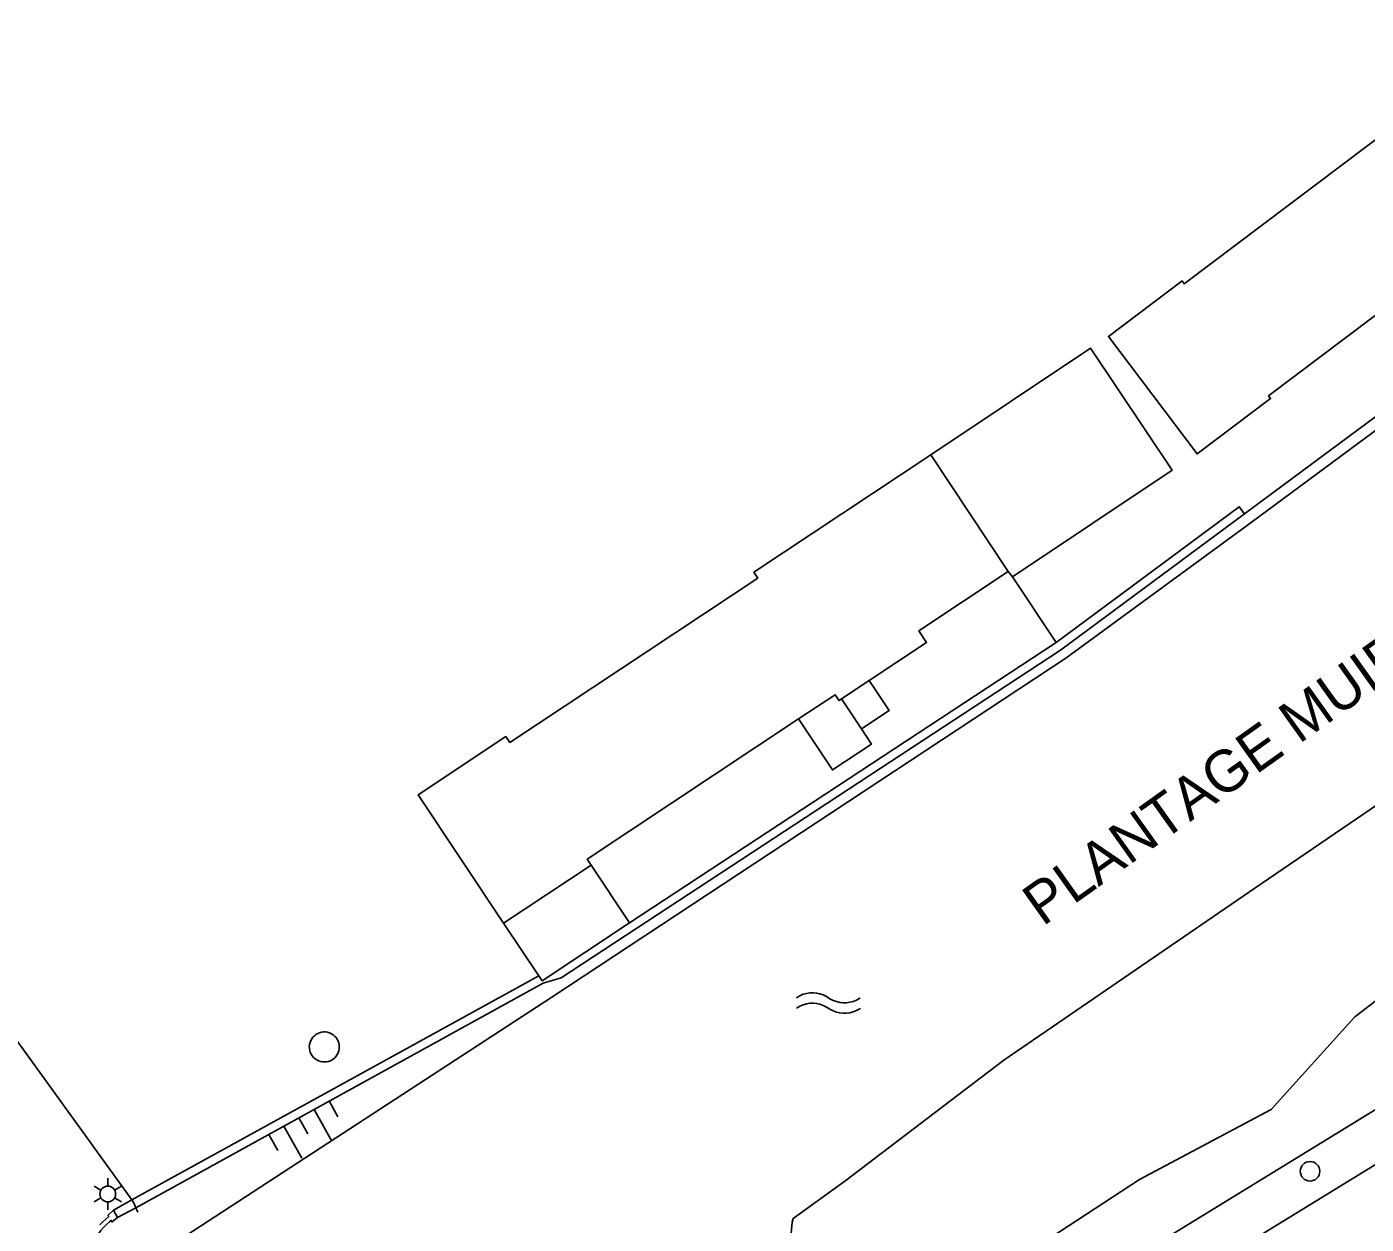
# Model space of a CAD drawing. Extents: x 122462 to 123306, y 485548 to 486417.
# Drawn here: x 123082 to 123158.7, y 486348.4 to 486417 of the extents above; entities that cross this region are included whole.
import ezdxf

# ---------------------------------------------------------------- set-up
doc = ezdxf.new("R2010")
doc.units = 0
for name, color, linetype in [('Level 1', 7, 'Continuous'), ('Level 15', 7, 'Continuous'), ('Level 16', 7, 'Continuous'), ('Level 17', 7, 'Continuous'), ('Level 19', 7, 'Continuous'), ('Level 2', 7, 'Continuous'), ('Level 20', 7, 'Continuous'), ('Level 24', 7, 'Continuous'), ('Level 41', 7, 'Continuous'), ('Level 50', 7, 'Continuous'), ('Level 53', 7, 'Continuous'), ('Level 55', 7, 'Continuous'), ('Level 57', 7, 'Continuous'), ('N werkgrens', 7, 'Continuous'), ('N-WE-GR-BOOM_STAM-G', 7, 'Continuous')]:
    doc.layers.add(name, color=color, linetype=linetype)

msp = doc.modelspace()

# ---------------------------------------------------------------- linework, layer by layer
at = {"layer": 'Level 1'}
msp.add_lwpolyline([(123167.795, 486416.958), (123166.225, 486415.776), (123166.105, 486415.936), (123160.112, 486411.424), (123160.232, 486411.265), (123148.252, 486402.244), (123148.132, 486402.404), (123143.918, 486399.231), (123148.989, 486392.497), (123153.203, 486395.67), (123153.083, 486395.83), (123165.062, 486404.849), (123165.182, 486404.69), (123171.175, 486409.202), (123171.055, 486409.362), (123181.145, 486416.958)], dxfattribs=at)
at = {"layer": 'Level 15'}
for p, q in [((123116.491, 486365.658), (123140.926, 486381.7)), ((123088.001, 486349.781), (123111.309, 486362.623)), ((123086.952, 486349.203), (123088.001, 486349.781)), ((123088.234, 486349.339), (123087.19, 486348.785)), ((123087.19, 486348.785), (123086.952, 486349.203))]:
    msp.add_line(p, q, dxfattribs=at)
for points in [[(123140.926, 486381.7), (123151.405, 486389.472), (123151.706, 486389.073)], [(123151.706, 486389.073), (123141.17, 486381.258), (123112.593, 486362.502), (123111.563, 486362.191), (123088.234, 486349.339)], [(123087.19, 486348.785), (123086.875, 486348.525), (123086.834, 486348.614), (123086.725, 486348.527), (123086.553, 486348.374), (123086.393, 486348.209), (123086.243, 486348.034), (123086.106, 486347.849), (123085.982, 486347.655), (123085.872, 486347.454), (123085.775, 486347.245), (123085.693, 486347.03), (123085.626, 486346.81), (123085.574, 486346.586), (123085.537, 486346.359), (123085.516, 486346.129), (123085.511, 486345.899), (123085.521, 486345.67), (123085.547, 486345.441), (123085.588, 486345.215), (123085.645, 486344.992), (123085.717, 486344.773), (123085.803, 486344.56), (123085.904, 486344.353)], [(123086.952, 486349.203), (123086.635, 486348.888), (123086.691, 486348.832), (123086.516, 486348.691), (123086.339, 486348.528), (123086.173, 486348.354)]]:
    msp.add_lwpolyline(points, dxfattribs=at)
at = {"layer": 'Level 16'}
for points in [[(123190.452, 486416.958), (123152.084, 486388.57), (123141.474, 486380.8), (123112.044, 486361.399), (123104.38, 486356.401), (123085.904, 486344.353)], [(123217.361, 486416.958), (123206.829, 486406.748), (123179.003, 486385.844), (123152.655, 486367.889), (123137.927, 486357.79), (123128.826, 486350.852), (123125.877, 486348.714), (123125.807, 486348.517), (123125.744, 486347.678)]]:
    msp.add_lwpolyline(points, dxfattribs=at)
at = {"layer": 'Level 17'}
for points in [[(123132.782, 486338.745), (123187.402, 486372.258)], [(123134.337, 486336.539), (123186.289, 486368.432)]]:
    msp.add_lwpolyline(points, dxfattribs=at)
at = {"layer": 'Level 19'}
for p, q in [((123189.359, 486416.958), (123151.706, 486389.073)), ((123138.417, 486385.457), (123140.926, 486381.7))]:
    msp.add_line(p, q, dxfattribs=at)
at = {"layer": 'Level 2'}
for p, q in [((123138.185, 486385.758), (123133.752, 486392.442)), ((123138.417, 486385.457), (123138.185, 486385.758)), ((123128.636, 486378.469), (123130.227, 486379.525)), ((123129.777, 486376.749), (123128.636, 486378.469)), ((123109.28, 486365.632), (123114.3, 486368.961)), ((123114.3, 486368.961), (123116.491, 486365.658)), ((123111.309, 486362.623), (123109.28, 486365.632))]:
    msp.add_line(p, q, dxfattribs=at)
for points in [[(123133.752, 486392.442), (123142.9, 486398.551), (123147.565, 486391.566), (123138.417, 486385.457)], [(123109.28, 486365.632), (123104.405, 486372.982), (123109.427, 486376.312), (123109.648, 486375.978), (123123.844, 486385.392), (123123.623, 486385.725), (123133.752, 486392.442)], [(123138.185, 486385.758), (123133.069, 486382.365), (123133.509, 486381.702), (123130.227, 486379.525)], [(123130.227, 486379.525), (123131.368, 486377.804), (123129.777, 486376.749)], [(123126.182, 486377.322), (123128.276, 486378.711), (123128.498, 486378.378), (123128.636, 486378.469)], [(123114.3, 486368.961), (123114.079, 486369.295), (123126.182, 486377.322)], [(123129.777, 486376.749), (123130.349, 486375.887), (123128.116, 486374.406), (123126.182, 486377.322)], [(123116.491, 486365.658), (123111.502, 486362.337), (123111.309, 486362.623)]]:
    msp.add_lwpolyline(points, dxfattribs=at)
at = {"layer": 'Level 20'}
msp.add_lwpolyline([(123227.128, 486416.958), (123226.347, 486416.118), (123214.358, 486404.642), (123207.4, 486399.966), (123200.277, 486394.449), (123191.597, 486386.324), (123182.341, 486378.222), (123175.379, 486372.758), (123164.712, 486365.388), (123158.016, 486360.276), (123153.237, 486354.953), (123145.688, 486350.946), (123140.068, 486347.272), (123131.328, 486340.807)], dxfattribs=at)
at = {"layer": 'Level 24'}
msp.add_line((123088.345, 486349.073), (123088.234, 486349.339), dxfattribs=at)
msp.add_lwpolyline([(123088.234, 486349.339), (123088.117, 486349.62), (123088.001, 486349.781)], dxfattribs=at)
at = {"layer": 'Level 41'}
msp.add_lwpolyline([(123099.038, 486357.684), (123098.923, 486357.691), (123098.809, 486357.712), (123098.699, 486357.75), (123098.596, 486357.801), (123098.5, 486357.866), (123098.414, 486357.943), (123098.339, 486358.031), (123098.276, 486358.129), (123098.227, 486358.234), (123098.193, 486358.344), (123098.174, 486358.458), (123098.17, 486358.574), (123098.182, 486358.689), (123098.21, 486358.802), (123098.252, 486358.909), (123098.308, 486359.011), (123098.378, 486359.103), (123098.459, 486359.186), (123098.55, 486359.256), (123098.651, 486359.314), (123098.758, 486359.358), (123098.87, 486359.387), (123098.985, 486359.401), (123099.101, 486359.399), (123099.215, 486359.381), (123099.326, 486359.349), (123099.432, 486359.301), (123099.53, 486359.24), (123099.619, 486359.166), (123099.698, 486359.081), (123099.764, 486358.986), (123099.817, 486358.883), (123099.856, 486358.774), (123099.879, 486358.661), (123099.887, 486358.545), (123099.88, 486358.43), (123099.857, 486358.316), (123099.819, 486358.207), (123099.767, 486358.104), (123099.701, 486358.009), (123099.623, 486357.923), (123099.478, 486357.811), (123099.376, 486357.757), (123099.267, 486357.718), (123099.154, 486357.693), (123099.038, 486357.684)], dxfattribs=at)
at = {"layer": 'Level 50'}
for p, q in [((123086.633, 486350.571), (123086.633, 486351.021)), ((123086.243, 486350.346), (123085.853, 486350.571)), ((123087.412, 486350.571), (123087.022, 486350.346)), ((123086.243, 486349.896), (123085.853, 486349.671)), ((123086.633, 486349.221), (123086.633, 486349.671)), ((123087.412, 486349.671), (123087.022, 486349.896))]:
    msp.add_line(p, q, dxfattribs=at)
msp.add_circle((123086.633, 486350.121), 0.45, dxfattribs=at)
at = {"layer": 'Level 53'}
msp.add_circle((123155.459, 486351.425), 0.56, dxfattribs=at)
at = {"layer": 'Level 55'}
for points in [[(123126.069, 486361.361), (123126.259, 486361.475), (123126.449, 486361.556), (123126.639, 486361.611), (123126.829, 486361.641), (123127.019, 486361.648), (123127.209, 486361.631), (123127.399, 486361.591), (123127.589, 486361.525), (123127.779, 486361.43), (123127.969, 486361.307), (123128.159, 486361.209), (123128.349, 486361.139), (123128.539, 486361.096), (123128.729, 486361.076), (123128.919, 486361.078), (123129.109, 486361.103), (123129.299, 486361.153), (123129.489, 486361.229), (123129.679, 486361.335), (123129.714, 486361.359)], [(123126.069, 486360.761), (123126.259, 486360.875), (123126.449, 486360.956), (123126.639, 486361.011), (123126.829, 486361.041), (123127.019, 486361.048), (123127.209, 486361.031), (123127.399, 486360.991), (123127.589, 486360.925), (123127.779, 486360.83), (123127.969, 486360.707), (123128.159, 486360.609), (123128.349, 486360.539), (123128.539, 486360.496), (123128.729, 486360.476), (123128.919, 486360.478), (123129.109, 486360.503), (123129.299, 486360.553), (123129.489, 486360.629), (123129.679, 486360.735), (123129.714, 486360.759)]]:
    msp.add_lwpolyline(points, dxfattribs=at)
at = {"layer": 'Level 57'}
for p, q in [((123099.299, 486355.448), (123099.81, 486354.534)), ((123098.438, 486354.967), (123099.459, 486353.139)), ((123096.716, 486354.005), (123097.737, 486352.178)), ((123097.577, 486354.486), (123098.088, 486353.572)), ((123095.856, 486353.524), (123096.366, 486352.61))]:
    msp.add_line(p, q, dxfattribs=at)
at = {"layer": 'N werkgrens'}
msp.add_lwpolyline([(123088.001, 486349.781), (123081.029, 486359.472)], dxfattribs=at)

# ---------------------------------------------------------------- texts
at = {"layer": 'N-WE-GR-BOOM_STAM-G'}
msp.add_text('PLANTAGE MUIDERGRACHT', height=2.4, rotation=35.45548, dxfattribs=at).set_placement((123140.153, 486365.414))

doc.saveas('drawing.dxf')
